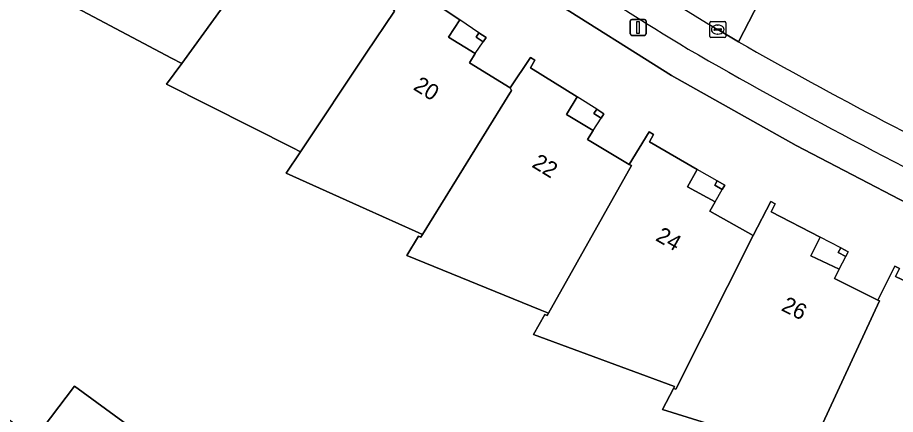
# Model space of a CAD drawing. Extents: x 163266 to 164362, y 381528 to 382286.
# Drawn here: x 163978.2 to 164033.1, y 382051.1 to 382075.9 of the extents above; entities that cross this region are included whole.
import ezdxf

# ---------------------------------------------------------------- set-up
doc = ezdxf.new("R2010")
doc.units = 0
for name, color, linetype in [('IMGEO_Erf', 7, 'Continuous'), ('IMGEO_Kolk', 7, 'Continuous'), ('IMGEO_Lichtmast', 7, 'Continuous'), ('IMGEO_Pand', 7, 'Continuous'), ('IMGEO_Pand_nummerreeks', 7, 'Continuous'), ('IMGEO_Pand_overbouw', 7, 'Continuous'), ('IMGEO_Parkeervlak_open', 7, 'Continuous'), ('IMGEO_Rijbaan_lokaal_open', 7, 'Continuous'), ('IMGEO_Voetpad_open', 7, 'Continuous')]:
    doc.layers.add(name, color=color, linetype=linetype)

msp = doc.modelspace()

# ---------------------------------------------------------------- linework, layer by layer
at = {"layer": 'IMGEO_Erf'}
for points in [[(164040.069, 382061.177), (164037.434, 382062.442), (164026.92, 382067.895), (164019.118, 382072.286), (164011.629, 382077.008), (164003.484, 382082.618), (164000, 382085.233)], [(164027.274, 382048.661), (164018.547, 382051.364), (164019.237, 382052.689), (164019.304, 382052.818), (164010.469, 382056.066), (164011.179, 382057.32), (164011.327, 382057.26), (164011.412, 382057.412), (164010.896, 382057.622), (164002.549, 382061.018), (164003.275, 382062.232), (164003.421, 382062.166), (164003.526, 382062.336), (164003.064, 382062.544), (164000, 382063.923), (163994.986, 382066.181), (163995.878, 382067.516), (163995.407, 382067.753), (163987.493, 382071.743), (163988.438, 382073.046), (163987.8, 382073.385), (163980.126, 382077.457)], [(164002.971, 382077.693), (164005.866, 382075.769), (164005.153, 382074.696), (164006.827, 382073.658), (164006.455, 382073.089), (164009.003, 382071.509), (164010.292, 382073.421), (164010.561, 382073.243), (164010.291, 382072.775), (164013.203, 382070.947), (164012.533, 382069.849), (164014.202, 382068.834), (164013.858, 382068.271), (164016.475, 382066.724), (164017.72, 382068.756), (164017.999, 382068.598), (164017.744, 382068.13), (164020.729, 382066.397), (164020.115, 382065.321), (164021.845, 382064.368), (164021.523, 382063.795), (164024.227, 382062.276), (164025.334, 382064.402), (164025.616, 382064.252), (164025.359, 382063.755), (164028.425, 382062.172), (164027.844, 382061.002), (164029.616, 382060.169), (164029.328, 382059.572), (164032.042, 382058.22), (164033.103, 382060.347), (164033.389, 382060.206), (164033.142, 382059.704), (164036.288, 382058.228)], [(163977.299, 382054.083), (163975.818, 382052.069), (163979.25, 382049.545), (163981.719, 382052.842), (163986.146, 382049.588)]]:
    msp.add_lwpolyline(points, dxfattribs=at)
for points in [[(164007.054, 382074.966), (164007.5, 382074.663), (164007.325, 382074.396), (164006.879, 382074.699)], [(164014.431, 382070.177), (164014.885, 382069.896), (164014.71, 382069.624), (164014.256, 382069.905)], [(164021.985, 382065.693), (164022.448, 382065.431), (164022.291, 382065.156), (164021.828, 382065.418)], [(164029.714, 382061.497), (164030.189, 382061.245), (164030.038, 382060.959), (164029.563, 382061.211)]]:
    msp.add_lwpolyline(points, close=True, dxfattribs=at)
at = {"layer": 'IMGEO_Kolk'}
for p, q in [((164021.514, 382074.74), (164021.514, 382075.592)), ((164021.589, 382075.666), (164022.441, 382075.666)), ((164022.515, 382075.592), (164022.515, 382074.74)), ((164021.773, 382075.16), (164021.773, 382075.172)), ((164022.211, 382075.123), (164021.813, 382075.123)), ((164021.816, 382075.209), (164022.214, 382075.209)), ((164022.002, 382075.446), (164022.027, 382075.446)), ((164022.257, 382075.172), (164022.257, 382075.16)), ((164022.441, 382074.666), (164021.589, 382074.666)), ((164022.025, 382074.886), (164022, 382074.886))]:
    msp.add_line(p, q, dxfattribs=at)
for points in [[(164021.514, 382074.74), (164021.514, 382075.592)], [(164021.589, 382075.666), (164022.441, 382075.666)], [(164022.515, 382075.592), (164022.515, 382074.74)], [(164022.441, 382074.666), (164021.589, 382074.666)]]:
    msp.add_lwpolyline(points, dxfattribs=at)
for centre, radius, start, end in [((164021.591, 382075.59), 0.0765, 91.552, 178.448), ((164021.591, 382075.59), 0.0765, 91.552, 178.448), ((164022.439, 382075.59), 0.0765, 1.552, 88.448), ((164022.439, 382075.59), 0.0765, 1.552, 88.448), ((164021.813, 382075.169), 0.0403, 85.8775, 175.7526), ((164021.81, 382075.159), 0.0366, 178.938, 274.7102), ((164022.214, 382075.166), 0.043, 264.8664, 352.4533), ((164022.218, 382075.171), 0.0386, 1.7309, 96.639), ((164021.591, 382074.742), 0.0765, 181.552, 268.448), ((164021.591, 382074.742), 0.0765, 181.552, 268.448), ((164022.439, 382074.742), 0.0765, 271.552, 358.448), ((164022.439, 382074.742), 0.0765, 271.552, 358.448)]:
    msp.add_arc(centre, radius, start, end, dxfattribs=at)
for centre, major_axis, ratio, start_param, end_param in [((164022.001, 382075.166), (-0.387, 0.002), 0.722429, 4.712389, 7.853982), ((164022.026, 382075.166), (-0.39, 0.002), 0.717154, 1.570796, 4.712389)]:
    msp.add_ellipse(centre, major_axis=major_axis, ratio=ratio, start_param=start_param, end_param=end_param, dxfattribs=at)
at = {"layer": 'IMGEO_Lichtmast'}
for p, q in [((164016.531, 382074.903), (164016.531, 382075.703)), ((164016.531, 382075.703), (164016.531, 382074.903)), ((164016.631, 382075.803), (164017.421, 382075.803)), ((164017.421, 382075.803), (164016.631, 382075.803)), ((164017.521, 382075.703), (164017.521, 382074.903)), ((164017.521, 382074.903), (164017.521, 382075.703)), ((164017.421, 382074.803), (164016.631, 382074.803)), ((164016.631, 382074.803), (164017.421, 382074.803))]:
    msp.add_line(p, q, dxfattribs=at)
msp.add_lwpolyline([(164016.951, 382075.678), (164017.101, 382075.678), (164017.101, 382074.928), (164016.951, 382074.928), (164016.951, 382075.678)], dxfattribs=at)
for centre, start, end in [((164016.631, 382075.703), 90, 180), ((164016.631, 382075.703), 90, 180), ((164017.421, 382075.703), 0, 90), ((164017.421, 382075.703), 360, 90), ((164016.631, 382074.903), 180, 270), ((164016.631, 382074.903), 180, 270), ((164017.421, 382074.903), 270, 0), ((164017.421, 382074.903), 270, 0)]:
    msp.add_arc(centre, 0.1, start, end, dxfattribs=at)
at = {"layer": 'IMGEO_Pand'}
for points in [[(163994.665, 382081.632), (163992.14, 382083.542), (163992.538, 382084.044), (163990.955, 382085.242), (163991.75, 382086.229), (163989.06, 382088.391), (163989.385, 382088.822), (163989.264, 382088.923), (163981.142, 382078.732), (163980.126, 382077.457), (163987.8, 382073.385), (163988.438, 382073.046)], [(164001.766, 382076.325), (164001.668, 382076.463), (164000, 382077.614), (163999.197, 382078.168), (163999.581, 382078.716), (163997.945, 382079.853), (163998.709, 382080.879), (163995.935, 382082.978), (163996.245, 382083.363), (163996.036, 382083.522), (163994.665, 382081.632), (163988.438, 382073.046), (163987.493, 382071.743), (163995.407, 382067.753), (163995.878, 382067.516), (164000, 382073.683)], [(164009.086, 382071.347), (164009.003, 382071.509), (164006.455, 382073.089), (164006.827, 382073.658), (164005.153, 382074.696), (164005.866, 382075.769), (164002.971, 382077.693), (164003.31, 382078.163), (164003.05, 382078.342), (164001.668, 382076.463), (164001.766, 382076.325), (164000, 382073.683), (163995.878, 382067.516), (163994.986, 382066.181), (164000, 382063.923), (164003.064, 382062.544), (164003.526, 382062.336)], [(164007.054, 382074.966), (164006.879, 382074.699), (164007.325, 382074.396), (164007.5, 382074.663)], [(164016.602, 382066.645), (164016.475, 382066.724), (164013.858, 382068.271), (164014.202, 382068.834), (164012.533, 382069.849), (164013.203, 382070.947), (164010.291, 382072.775), (164010.561, 382073.243), (164010.292, 382073.421), (164009.003, 382071.509), (164009.086, 382071.347), (164003.526, 382062.336), (164003.421, 382062.166), (164003.275, 382062.232), (164002.549, 382061.018), (164010.896, 382057.622), (164011.412, 382057.412)], [(164014.431, 382070.177), (164014.256, 382069.905), (164014.71, 382069.624), (164014.885, 382069.896)], [(164024.227, 382062.276), (164021.523, 382063.795), (164021.845, 382064.368), (164020.115, 382065.321), (164020.729, 382066.397), (164017.744, 382068.13), (164017.999, 382068.598), (164017.72, 382068.756), (164016.475, 382066.724), (164016.602, 382066.645), (164011.412, 382057.412), (164011.327, 382057.26), (164011.179, 382057.32), (164010.469, 382056.066), (164019.304, 382052.818), (164019.237, 382052.689), (164019.38, 382052.637)], [(164022.448, 382065.431), (164021.985, 382065.693), (164021.828, 382065.418), (164022.291, 382065.156)], [(164032.141, 382058.171), (164032.042, 382058.22), (164029.328, 382059.572), (164029.616, 382060.169), (164027.844, 382061.002), (164028.425, 382062.172), (164025.359, 382063.755), (164025.616, 382064.252), (164025.334, 382064.402), (164024.227, 382062.276), (164019.38, 382052.637), (164019.237, 382052.689), (164018.547, 382051.364), (164027.274, 382048.661), (164027.68, 382048.535)], [(164030.189, 382061.245), (164029.714, 382061.497), (164029.563, 382061.211), (164030.038, 382060.959)], [(164040.358, 382054.205), (164037.279, 382055.681), (164037.56, 382056.281), (164035.748, 382057.131), (164036.288, 382058.228), (164033.142, 382059.704), (164033.389, 382060.206), (164033.103, 382060.347), (164032.042, 382058.22), (164032.141, 382058.171), (164027.68, 382048.535), (164027.599, 382048.361), (164027.447, 382048.409), (164026.833, 382047.109), (164036.26, 382044.384), (164037.634, 382047.251), (164037.138, 382047.488)], [(163987.69, 382046.445), (163985.176, 382048.293), (163986.146, 382049.588), (163981.719, 382052.842), (163979.25, 382049.545), (163974.008, 382042.545), (163973.088, 382041.317), (163977.074, 382038.381), (163977.268, 382038.646), (163977.049, 382038.808), (163977.775, 382039.793), (163978.629, 382039.161), (163981.405, 382042.943), (163983.818, 382041.16)]]:
    msp.add_lwpolyline(points, close=True, dxfattribs=at)
at = {"layer": 'IMGEO_Pand_overbouw'}
for points in [[(164007.325, 382074.396), (164006.879, 382074.699), (164007.054, 382074.966), (164005.866, 382075.769), (164005.153, 382074.696), (164006.827, 382073.658)], [(164014.71, 382069.624), (164014.256, 382069.905), (164014.431, 382070.177), (164013.203, 382070.947), (164012.533, 382069.849), (164014.202, 382068.834)], [(164022.291, 382065.156), (164021.828, 382065.418), (164021.985, 382065.693), (164020.729, 382066.397), (164020.115, 382065.321), (164021.845, 382064.368)], [(164029.714, 382061.497), (164028.425, 382062.172), (164027.844, 382061.002), (164029.616, 382060.169), (164030.038, 382060.959), (164029.563, 382061.211)]]:
    msp.add_lwpolyline(points, close=True, dxfattribs=at)
at = {"layer": 'IMGEO_Parkeervlak_open'}
msp.add_lwpolyline([(164023.304, 382074.399), (164022.016, 382075.167)], dxfattribs=at)
for centre, radius, start, end in [((164138.268, 382270.123), 226.985, 232.47193, 239.19239), ((164137.096, 382267.365), 226.015, 233.8741, 238.84626), ((164169.2, 382331.075), 295.243, 240.38592, 244.42503), ((164180.344, 382351.285), 320.271, 239.99193, 244.19272)]:
    msp.add_arc(centre, radius, start, end, dxfattribs=at)
at = {"layer": 'IMGEO_Rijbaan_lokaal_open'}
for points in [[(164022.016, 382075.167), (164023.304, 382074.399), (164025.604, 382078.868), (164024.634, 382079.422)], [(164029.032, 382077.02), (164025.604, 382078.868), (164023.304, 382074.399)]]:
    msp.add_lwpolyline(points, dxfattribs=at)
for centre, radius, start, end in [((164138.268, 382270.123), 226.985, 232.47193, 239.19239), ((164169.2, 382331.075), 295.243, 240.38592, 244.42503)]:
    msp.add_arc(centre, radius, start, end, dxfattribs=at)
at = {"layer": 'IMGEO_Voetpad_open'}
msp.add_lwpolyline([(163979.756, 382126.893), (163977.832, 382118.691), (163975.495, 382108.964), (163975.044, 382107.165), (163975.025, 382107.091), (163978.602, 382103.308), (163984.98, 382097.44), (163989.156, 382093.775), (163996.064, 382088.188), (164000, 382085.233), (164003.484, 382082.618), (164011.629, 382077.008), (164019.118, 382072.286), (164026.92, 382067.895), (164037.434, 382062.442), (164040.069, 382061.177)], dxfattribs=at)
for centre, radius, start, end in [((164137.096, 382267.365), 226.015, 233.8741, 238.84626), ((164180.344, 382351.285), 320.271, 239.99193, 244.19272)]:
    msp.add_arc(centre, radius, start, end, dxfattribs=at)

# ---------------------------------------------------------------- texts
at = {"layer": 'IMGEO_Pand_nummerreeks'}
for s, rotation, p in [('20', 328.2008, (164002.885, 382071.443)), ('22', 328.5217, (164010.313, 382066.595)), ('24', 330.3838, (164018.06, 382061.99)), ('26', 333.5179, (164025.933, 382057.599))]:
    msp.add_text(s, height=1, rotation=rotation, dxfattribs=at).set_placement(p)

doc.saveas('drawing.dxf')
